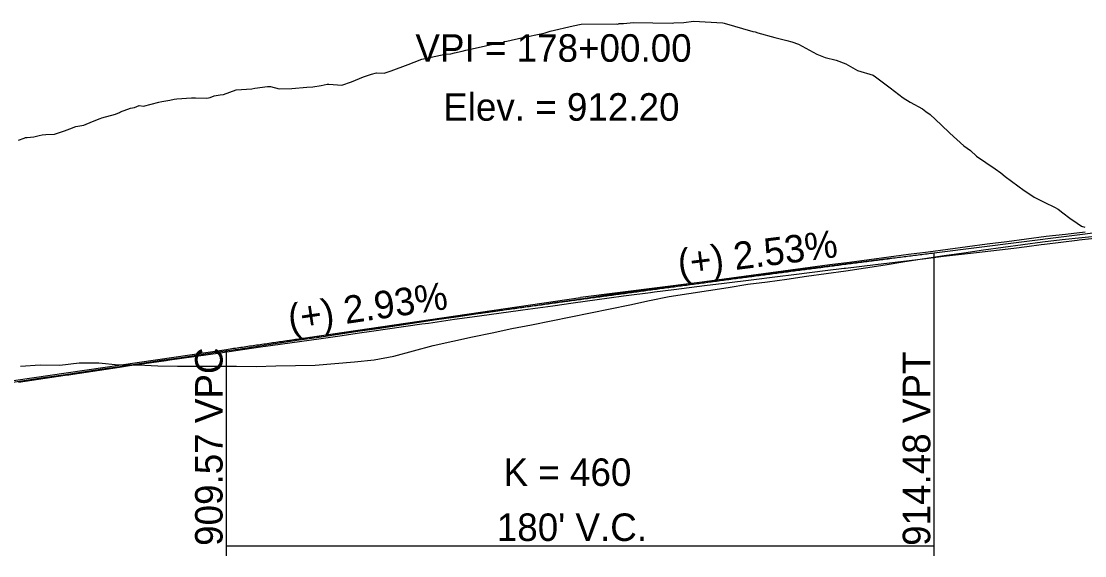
# Model space of a CAD drawing. Extents: x 1475774 to 1484571, y 1098511 to 1113011.
# Drawn here: x 1480428.8 to 1480699.3, y 1104006.6 to 1104142.5 of the extents above; entities that cross this region are included whole.
import ezdxf

# ---------------------------------------------------------------- set-up
doc = ezdxf.new("R2010")
doc.units = 0
for name, color, linetype in [('RD_DDB_GradeTX', 7, 'Continuous'), ('RD_DDB_PointTX', 7, 'Continuous'), ('RD_DDB_Profile_EX', 7, 'Continuous'), ('RD_DDB_Profile_Lbl', 7, 'Continuous'), ('RD_DDB_Profile_PR', 7, 'Continuous'), ('RD_DDB_StripGrade', 7, 'Continuous'), ('RD_DDB_VCLbl', 7, 'Continuous'), ('RD_Sketch2', 7, 'Continuous'), ('RD_Sketch3', 7, 'Continuous')]:
    doc.layers.add(name, color=color, linetype=linetype)

msp = doc.modelspace()

# ---------------------------------------------------------------- linework, layer by layer
at = {"layer": 'RD_DDB_GradeTX'}
for p in [(1480650.35, 1104082.3), (1480491.83, 1104060.67)]:
    msp.add_line(p, (1480570.98, 1104072.25), dxfattribs=at)
at = {"layer": 'RD_DDB_PointTX'}
for points in [[(1480664.42, 1104084.58), (1480669.42, 1104085.24), (1480674.42, 1104085.9), (1480679.42, 1104086.56), (1480684.42, 1104087.22), (1480689.42, 1104087.86), (1480694.42, 1104088.43), (1480699.42, 1104089.01)], [(1480424.42, 1104050.43), (1480429.42, 1104051.16), (1480434.42, 1104051.89), (1480439.42, 1104052.63), (1480444.42, 1104053.36), (1480449.42, 1104054.1), (1480454.42, 1104054.83), (1480459.42, 1104055.57), (1480464.42, 1104056.31), (1480469.42, 1104057.04), (1480474.42, 1104057.78), (1480479.42, 1104058.51), (1480484.42, 1104059.25), (1480489.42, 1104059.99), (1480494.42, 1104060.73), (1480499.42, 1104061.47), (1480504.42, 1104062.21), (1480509.42, 1104062.95), (1480514.42, 1104063.69), (1480519.42, 1104064.43), (1480524.42, 1104065.16), (1480529.42, 1104065.9), (1480534.42, 1104066.64), (1480539.42, 1104067.38), (1480544.42, 1104068.1), (1480549.42, 1104068.83), (1480554.42, 1104069.55), (1480559.42, 1104070.28), (1480564.42, 1104071), (1480569.42, 1104071.72), (1480574.42, 1104072.45), (1480579.42, 1104073.17), (1480584.42, 1104073.9), (1480589.42, 1104074.59), (1480594.42, 1104075.26), (1480599.42, 1104075.94), (1480604.42, 1104076.61), (1480609.42, 1104077.28), (1480614.42, 1104077.95), (1480619.42, 1104078.62), (1480624.42, 1104079.29), (1480629.42, 1104079.96), (1480634.42, 1104080.64), (1480639.42, 1104081.29), (1480644.42, 1104081.95), (1480649.42, 1104082.61), (1480654.42, 1104083.27), (1480659.42, 1104083.93), (1480664.42, 1104084.58)]]:
    msp.add_lwpolyline(points, dxfattribs=at)
at = {"layer": 'RD_DDB_Profile_EX'}
for points in [[(1480663.54, 1104082.94), (1480668.54, 1104083.67), (1480673.54, 1104084.37), (1480678.54, 1104085.07), (1480683.54, 1104085.77), (1480688.54, 1104086.47), (1480693.54, 1104087), (1480698.54, 1104087.54), (1480703.54, 1104088.07)], [(1480428.54, 1104054.8), (1480433.54, 1104055.18), (1480438.54, 1104055.08), (1480443.54, 1104055.66), (1480448.54, 1104055.66), (1480453.54, 1104055.18), (1480458.54, 1104055.17), (1480463.54, 1104054.88), (1480468.54, 1104054.85), (1480473.54, 1104054.79), (1480478.54, 1104054.83), (1480483.54, 1104054.79), (1480488.54, 1104054.75), (1480493.54, 1104054.93), (1480498.54, 1104055.01), (1480503.54, 1104055.05), (1480508.54, 1104055.48), (1480513.54, 1104055.95), (1480518.54, 1104056.42), (1480523.54, 1104057.32), (1480528.54, 1104058.74), (1480533.54, 1104060.03), (1480538.54, 1104061.21), (1480543.54, 1104062.28), (1480548.54, 1104063.33), (1480553.54, 1104064.38), (1480558.54, 1104065.34), (1480563.54, 1104066.34), (1480568.54, 1104067.33), (1480573.54, 1104068.34), (1480578.54, 1104069.36), (1480583.54, 1104070.42), (1480588.54, 1104071.48), (1480593.54, 1104072.5), (1480598.54, 1104073.32), (1480603.54, 1104074.07), (1480608.54, 1104074.86), (1480613.54, 1104075.64), (1480618.54, 1104076.26), (1480623.54, 1104076.95), (1480628.54, 1104077.68), (1480633.54, 1104078.4), (1480638.54, 1104079.02), (1480643.54, 1104079.85), (1480648.54, 1104080.62), (1480653.54, 1104081.4), (1480658.54, 1104082.17), (1480663.54, 1104082.94)]]:
    msp.add_lwpolyline(points, dxfattribs=at)
at = {"layer": 'RD_DDB_Profile_PR'}
for p, q in [((1480660.98, 1104083.65), (1480735.98, 1104093.15)), ((1480420.98, 1104050.31), (1480480.98, 1104059.09)), ((1480420.98, 1104050.31), (1480480.98, 1104059.09))]:
    msp.add_line(p, q, dxfattribs=at)
msp.add_spline([(1480480.98, 1104059.09), (1480484.58, 1104059.61), (1480488.18, 1104060.14), (1480491.78, 1104060.66), (1480495.38, 1104061.18), (1480498.98, 1104061.7), (1480502.58, 1104062.22), (1480506.18, 1104062.74), (1480509.78, 1104063.25), (1480513.38, 1104063.77), (1480516.98, 1104064.28), (1480520.58, 1104064.79), (1480524.18, 1104065.3), (1480527.78, 1104065.81), (1480531.38, 1104066.32), (1480534.98, 1104066.82), (1480538.58, 1104067.33), (1480542.18, 1104067.83), (1480545.78, 1104068.33), (1480549.38, 1104068.83), (1480552.98, 1104069.33), (1480556.58, 1104069.83), (1480560.18, 1104070.33), (1480563.78, 1104070.82), (1480567.38, 1104071.32), (1480570.98, 1104071.81), (1480574.58, 1104072.3), (1480578.18, 1104072.79), (1480581.78, 1104073.27), (1480585.38, 1104073.76), (1480588.98, 1104074.25), (1480592.58, 1104074.73), (1480596.18, 1104075.21), (1480599.78, 1104075.69), (1480603.38, 1104076.17), (1480606.98, 1104076.65), (1480610.58, 1104077.13), (1480614.18, 1104077.6), (1480617.78, 1104078.07), (1480621.38, 1104078.55), (1480624.98, 1104079.02), (1480628.58, 1104079.49), (1480632.18, 1104079.95), (1480635.78, 1104080.42), (1480639.38, 1104080.89), (1480642.98, 1104081.35), (1480646.58, 1104081.81), (1480650.18, 1104082.27), (1480653.78, 1104082.73), (1480657.38, 1104083.19), (1480660.98, 1104083.65)], degree=3, dxfattribs=at)
msp.add_spline([(1480480.98, 1104059.09), (1480484.58, 1104059.61), (1480488.18, 1104060.14), (1480491.78, 1104060.66), (1480495.38, 1104061.18), (1480498.98, 1104061.7), (1480502.58, 1104062.22), (1480506.18, 1104062.74), (1480509.78, 1104063.25), (1480513.38, 1104063.77), (1480516.98, 1104064.28), (1480520.58, 1104064.79), (1480524.18, 1104065.3), (1480527.78, 1104065.81), (1480531.38, 1104066.32), (1480534.98, 1104066.82), (1480538.58, 1104067.33), (1480542.18, 1104067.83), (1480545.78, 1104068.33), (1480549.38, 1104068.83), (1480552.98, 1104069.33), (1480556.58, 1104069.83), (1480560.18, 1104070.33), (1480563.78, 1104070.82), (1480567.38, 1104071.32), (1480570.98, 1104071.81), (1480574.58, 1104072.3), (1480578.18, 1104072.79), (1480581.78, 1104073.27), (1480585.38, 1104073.76), (1480588.98, 1104074.25), (1480592.58, 1104074.73), (1480596.18, 1104075.21), (1480599.78, 1104075.69), (1480603.38, 1104076.17), (1480606.98, 1104076.65), (1480610.58, 1104077.13), (1480614.18, 1104077.6), (1480617.78, 1104078.07), (1480621.38, 1104078.55), (1480624.98, 1104079.02), (1480628.58, 1104079.49), (1480632.18, 1104079.95), (1480635.78, 1104080.42), (1480639.38, 1104080.89), (1480642.98, 1104081.35), (1480646.58, 1104081.81), (1480650.18, 1104082.27), (1480653.78, 1104082.73), (1480657.38, 1104083.19), (1480660.98, 1104083.65)], degree=3, dxfattribs=at)
at = {"layer": 'RD_DDB_VCLbl'}
for p, q in [((1480660.98, 1104006.59), (1480660.98, 1104083.65)), ((1480660.98, 1104006.59), (1480660.98, 1104083.65)), ((1480660.98, 1104006.59), (1480660.98, 1104083.65)), ((1480660.98, 1104006.59), (1480660.98, 1104083.65)), ((1480480.98, 1104006.59), (1480480.98, 1104059.09)), ((1480480.98, 1104009.09), (1480660.98, 1104009.09)), ((1480660.98, 1104009.09), (1480660.98, 1104009.09)), ((1480660.98, 1104009.09), (1480660.98, 1104009.09)), ((1480660.98, 1104009.09), (1480660.98, 1104009.09))]:
    msp.add_line(p, q, dxfattribs=at)
at = {"layer": 'RD_Sketch2'}
msp.add_lwpolyline([(1480428.08, 1104050.71), (1480439.91, 1104052.49), (1480440.9, 1104052.64), (1480441.92, 1104052.79), (1480453.72, 1104054.58), (1480456.33, 1104054.97), (1480465.61, 1104056.29), (1480466.55, 1104056.42), (1480479.37, 1104058.23), (1480489.66, 1104059.69), (1480492.19, 1104060.05), (1480505.02, 1104061.88), (1480509.8, 1104062.56), (1480514.82, 1104063.28), (1480517.84, 1104063.71), (1480530.66, 1104065.54), (1480532.34, 1104065.78), (1480538.98, 1104066.74), (1480543.48, 1104067.37), (1480555.18, 1104069.01), (1480556.31, 1104069.16), (1480564.02, 1104070.18), (1480569.13, 1104070.89), (1480578.31, 1104072.18), (1480581.95, 1104072.66), (1480588.83, 1104073.57), (1480589.83, 1104073.7), (1480594.78, 1104074.34), (1480602.55, 1104075.34), (1480607.6, 1104075.95), (1480615.07, 1104076.85), (1480620.42, 1104077.53), (1480625.96, 1104078.24), (1480633.24, 1104079.12), (1480638.08, 1104079.7), (1480638.44, 1104079.75), (1480646.07, 1104080.65), (1480654.62, 1104081.66), (1480658.89, 1104082.19), (1480663.34, 1104082.75), (1480671.71, 1104083.73), (1480681.27, 1104084.86), (1480684.54, 1104085.27), (1480688.23, 1104085.73), (1480689.02, 1104085.82), (1480697.36, 1104086.86), (1480697.89, 1104086.92), (1480704.09, 1104087.6)], dxfattribs=at)
at = {"layer": 'RD_Sketch3'}
msp.add_lwpolyline([(1480428.08, 1104112.3), (1480429.48, 1104112.8), (1480429.83, 1104113), (1480430.27, 1104113.01), (1480431.97, 1104113.11), (1480433.35, 1104113.46), (1480434.1, 1104113.67), (1480435.02, 1104113.73), (1480437.22, 1104113.85), (1480439.77, 1104114.64), (1480441.1, 1104115.2), (1480442.64, 1104115.74), (1480444.68, 1104116.09), (1480446.9, 1104117.04), (1480448.84, 1104117.85), (1480449.29, 1104118), (1480452.71, 1104118.94), (1480453.72, 1104119.35), (1480454.04, 1104119.47), (1480456.58, 1104120.44), (1480457.58, 1104120.64), (1480458.8, 1104121.15), (1480459.89, 1104120.93), (1480463.74, 1104121.97), (1480464.55, 1104122.12), (1480466.55, 1104122.51), (1480467.62, 1104122.72), (1480468.32, 1104122.81), (1480472.06, 1104123.05), (1480472.52, 1104123.1), (1480473.09, 1104123.06), (1480475.93, 1104122.95), (1480476.79, 1104123.15), (1480477.85, 1104123.62), (1480479.37, 1104123.82), (1480480.21, 1104123.93), (1480483.46, 1104125.14), (1480487.43, 1104125.39), (1480488.14, 1104125.52), (1480491.39, 1104125.94), (1480491.73, 1104125.98), (1480492.19, 1104125.95), (1480494.34, 1104125.35), (1480497.56, 1104125.46), (1480501.43, 1104125.77), (1480502.91, 1104125.87), (1480505.02, 1104126.24), (1480506.61, 1104126.51), (1480507.03, 1104126.54), (1480510.29, 1104126.32), (1480512.78, 1104127.12), (1480515.83, 1104128.39), (1480517.84, 1104129.05), (1480519.11, 1104129.47), (1480521.08, 1104129.38), (1480522.85, 1104129.95), (1480527.15, 1104131.51), (1480528.68, 1104132.14), (1480530.66, 1104132.91), (1480536.59, 1104134.18), (1480538.06, 1104134.27), (1480538.98, 1104134.49), (1480540.89, 1104134.92), (1480541.85, 1104135.21), (1480543.48, 1104135.56), (1480550.21, 1104137.03), (1480550.86, 1104137.15), (1480551.23, 1104137.18), (1480551.68, 1104137.39), (1480552.24, 1104137.52), (1480556.31, 1104138.38), (1480561.37, 1104139.45), (1480562.05, 1104139.59), (1480563.27, 1104140.01), (1480569.13, 1104141.39), (1480571.17, 1104141.78), (1480580.09, 1104141.9), (1480580.52, 1104141.81), (1480580.85, 1104142.01), (1480581.95, 1104141.99), (1480584.52, 1104142.24), (1480594.3, 1104142.09), (1480594.78, 1104142.12), (1480597.34, 1104142.21), (1480599.78, 1104142.55), (1480607.2, 1104142.18), (1480607.6, 1104142.1), (1480614.85, 1104139.96), (1480615.43, 1104139.9), (1480616.16, 1104139.62), (1480620.42, 1104138.46), (1480623.48, 1104137.63), (1480624.77, 1104137.34), (1480626.43, 1104136.75), (1480631.12, 1104134.17), (1480633.27, 1104133.32), (1480636.06, 1104132.67), (1480638.48, 1104131.72), (1480641.51, 1104130.01), (1480645.48, 1104128.82), (1480646.07, 1104128.44), (1480649.82, 1104125.65), (1480653.11, 1104123.09), (1480654.87, 1104121.99), (1480658.02, 1104120.27), (1480658.89, 1104119.63), (1480659.96, 1104118.84), (1480662.72, 1104116.2), (1480664.94, 1104114.11), (1480668.56, 1104110.9), (1480670.23, 1104109.68), (1480671.71, 1104108.22), (1480676.48, 1104105), (1480677.94, 1104103.98), (1480679.05, 1104103.07), (1480683.9, 1104099.49), (1480684.54, 1104099.06), (1480686.39, 1104097.79), (1480689.13, 1104096.48), (1480691.62, 1104095.28), (1480692.52, 1104094.78), (1480693.66, 1104093.85), (1480695.46, 1104092.42), (1480697.36, 1104091.18), (1480698.49, 1104090.45), (1480699.29, 1104090.14)], dxfattribs=at)

# ---------------------------------------------------------------- texts
at = {"layer": 'RD_DDB_GradeTX'}
for s, rotation, p in [('(+) 2.53%', 7.219, (1480596.2, 1104077.46)), ('(+) 2.93%', 8.3205, (1480497.15, 1104063.47))]:
    msp.add_text(s, height=7, rotation=rotation, dxfattribs=at).set_placement(p)
at = {"layer": 'RD_DDB_Profile_Lbl'}
for s, p in [('VPI = 178+00.00', (1480529.02, 1104132.25)), ('Elev. = 912.20', (1480536.09, 1104117.25))]:
    msp.add_text(s, height=7, dxfattribs=at).set_placement(p)
at = {"layer": 'RD_DDB_StripGrade'}
for s, p in [('909.57 VPC', (1480479.98, 1104009.09)), ('914.48 VPT', (1480659.98, 1104009.09)), ('914.48 VPT', (1480659.98, 1104009.09)), ('914.48 VPT', (1480659.98, 1104009.09)), ('914.48 VPT', (1480659.98, 1104009.09))]:
    msp.add_text(s, height=7, rotation=90, dxfattribs=at).set_placement(p)
at = {"layer": 'RD_DDB_VCLbl'}
for s, p in [('K = 460', (1480551.43, 1104024.34)), ("180' V.C.", (1480549.73, 1104010.34))]:
    msp.add_text(s, height=7, dxfattribs=at).set_placement(p)

doc.saveas('drawing.dxf')
